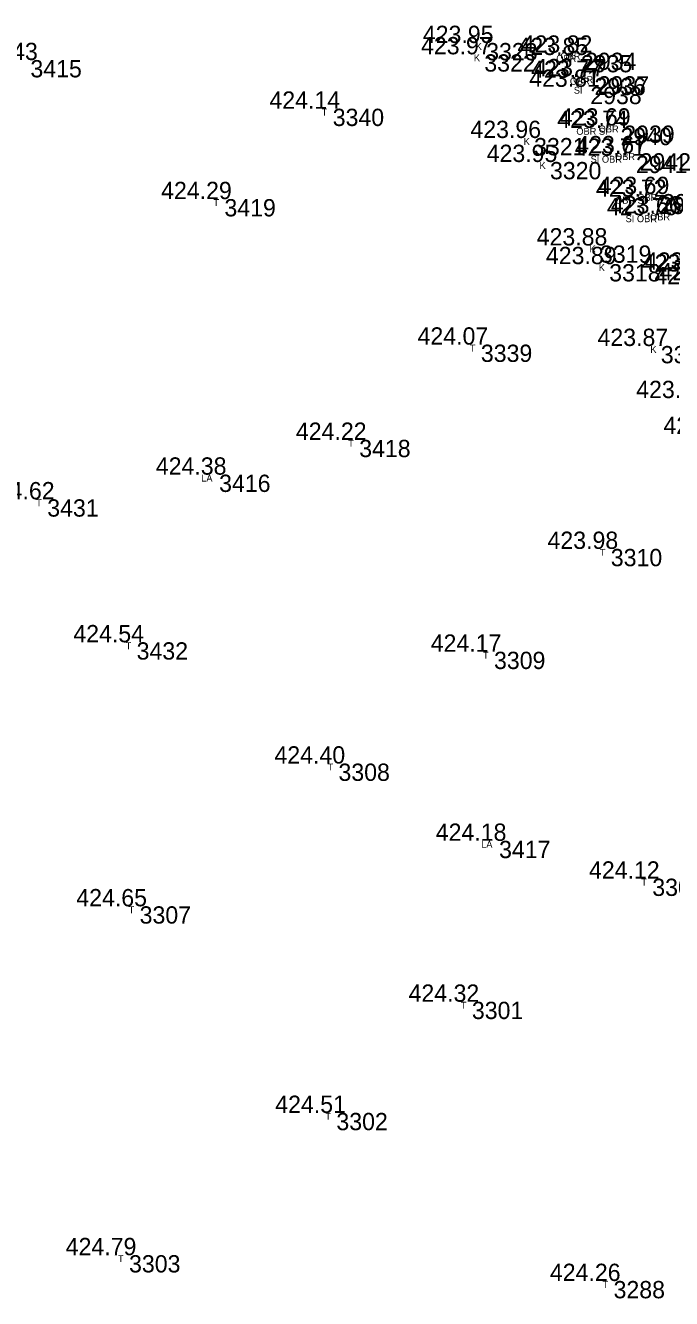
# Model space of a CAD drawing. Extents: x -639390 to -639075, y -1138747 to -1138358.
# Drawn here: x -639264.6 to -639236.5, y -1138514.5 to -1138459.3 of the extents above; entities that cross this region are included whole.
import ezdxf

# ---------------------------------------------------------------- set-up
doc = ezdxf.new("R2010")
doc.units = 0
for name, color, linetype in [('Vrstva 11', 7, 'Continuous'), ('Vrstva 12', 7, 'Continuous'), ('Vrstva 13', 7, 'Continuous'), ('Vrstva 57', 7, 'Continuous')]:
    doc.layers.add(name, color=color, linetype=linetype)

msp = doc.modelspace()

# ---------------------------------------------------------------- linework, layer by layer
at = {"layer": 'Vrstva 11'}
for p, q in [((-639244.92, -1138460.58), (-639244.92, -1138460.58)), ((-639244.84, -1138460.09), (-639244.84, -1138460.09)), ((-639240.73, -1138460.61), (-639240.73, -1138460.61)), ((-639240.55, -1138460.51), (-639240.55, -1138460.51)), ((-639240.14, -1138461.6), (-639240.14, -1138461.6)), ((-639240, -1138461.53), (-639240, -1138461.53)), ((-639240.32, -1138461.99), (-639240.32, -1138461.99)), ((-639251.5, -1138462.94), (-639251.5, -1138462.94)), ((-639239.01, -1138463.77), (-639239.01, -1138463.77)), ((-639238.89, -1138463.67), (-639238.89, -1138463.67)), ((-639242.76, -1138464.21), (-639242.76, -1138464.21)), ((-639238.34, -1138464.98), (-639238.34, -1138464.98)), ((-639238.18, -1138464.87), (-639238.18, -1138464.87)), ((-639242.07, -1138465.25), (-639242.07, -1138465.25)), ((-639237.21, -1138466.64), (-639237.21, -1138466.64)), ((-639256.2, -1138466.86), (-639256.2, -1138466.86)), ((-639237.33, -1138466.76), (-639237.33, -1138466.76)), ((-639236.82, -1138467.56), (-639236.82, -1138467.56)), ((-639236.66, -1138467.48), (-639236.66, -1138467.48)), ((-639239.9, -1138468.87), (-639239.9, -1138468.87)), ((-639239.5, -1138469.68), (-639239.5, -1138469.68)), ((-639245.07, -1138473.17), (-639245.07, -1138473.17)), ((-639237.26, -1138473.23), (-639237.26, -1138473.23)), ((-639250.35, -1138477.3), (-639250.35, -1138477.3)), ((-639256.43, -1138478.81), (-639256.43, -1138478.81)), ((-639263.89, -1138479.88), (-639263.89, -1138479.88)), ((-639239.43, -1138482.03), (-639239.43, -1138482.03)), ((-639260.01, -1138486.08), (-639260.01, -1138486.08)), ((-639244.5, -1138486.49), (-639244.5, -1138486.49)), ((-639251.25, -1138491.34), (-639251.25, -1138491.34)), ((-639244.28, -1138494.69), (-639244.28, -1138494.69)), ((-639237.63, -1138496.33), (-639237.63, -1138496.33)), ((-639259.88, -1138497.53), (-639259.88, -1138497.53)), ((-639245.46, -1138501.67), (-639245.46, -1138501.67)), ((-639251.34, -1138506.49), (-639251.34, -1138506.49)), ((-639260.34, -1138512.66), (-639260.34, -1138512.66)), ((-639239.31, -1138513.78), (-639239.31, -1138513.78))]:
    msp.add_line(p, q, dxfattribs=at)

# ---------------------------------------------------------------- texts
at = {"layer": 'Vrstva 12'}
for s, p in [('423.95 ', (-639247.31, -1138460.09)), ('424.43 ', (-639267.089, -1138460.83)), ('423.97 ', (-639247.389, -1138460.58)), ('423.85 ', (-639243.2, -1138460.61)), ('423.82 ', (-639243.019, -1138460.51)), ('423.77 ', (-639242.609, -1138461.6)), ('423.77 ', (-639242.469, -1138461.53)), ('423.81 ', (-639242.695, -1138461.99)), ('424.14 ', (-639253.969, -1138462.94)), ('423.74 ', (-639241.479, -1138463.77)), ('423.69 ', (-639241.359, -1138463.67)), ('423.96 ', (-639245.246, -1138464.21)), ('423.95 ', (-639244.54, -1138465.25)), ('423.71 ', (-639240.715, -1138464.98)), ('423.67 ', (-639240.649, -1138464.87)), ('424.29 ', (-639258.669, -1138466.86)), ('423.72 ', (-639239.799, -1138466.76)), ('423.69 ', (-639239.679, -1138466.64)), ('423.70 ', (-639239.319, -1138467.56)), ('423.66 ', (-639239.146, -1138467.48)), ('423.88 ', (-639242.369, -1138468.87)), ('423.89 ', (-639241.969, -1138469.68)), ('423.66 ', (-639237.806, -1138470)), ('423.66 ', (-639237.676, -1138469.92)), ('423.64 ', (-639237.259, -1138470.55)), ('423.54 ', (-639237.039, -1138470.38)), ('424.07 ', (-639247.539, -1138473.17)), ('423.87 ', (-639239.729, -1138473.23)), ('423.84 ', (-639238.049, -1138475.49)), ('424.22 ', (-639252.819, -1138477.3)), ('423.82 ', (-639236.869, -1138477.05)), ('424.38 ', (-639258.899, -1138478.81)), ('424.62 ', (-639266.359, -1138479.88)), ('423.98 ', (-639241.899, -1138482.03)), ('424.54 ', (-639262.479, -1138486.08)), ('424.17 ', (-639246.969, -1138486.49)), ('424.40 ', (-639253.749, -1138491.34)), ('424.18 ', (-639246.749, -1138494.69)), ('424.12 ', (-639240.099, -1138496.33)), ('424.65 ', (-639262.35, -1138497.53)), ('424.32 ', (-639247.929, -1138501.67)), ('424.51 ', (-639253.715, -1138506.49)), ('424.79 ', (-639262.809, -1138512.66)), ('424.26 ', (-639241.796, -1138513.78))]:
    msp.add_text(s, height=0.75, dxfattribs=at).set_placement(p)
at = {"layer": 'Vrstva 13'}
for s, p in [(' 3323', (-639244.84, -1138460.84)), (' 3322', (-639244.92, -1138461.33)), (' 2935', (-639240.73, -1138461.36)), (' 2934', (-639240.55, -1138461.26)), (' 3415', (-639264.62, -1138461.58)), (' 2936', (-639240.14, -1138462.35)), (' 2937', (-639240, -1138462.28)), (' 2938', (-639240.32, -1138462.74)), (' 3340', (-639251.5, -1138463.69)), (' 2940', (-639239.01, -1138464.52)), (' 2939', (-639238.89, -1138464.42)), (' 3321', (-639242.76, -1138464.96)), (' 2941', (-639238.34, -1138465.73)), (' 2942', (-639238.18, -1138465.62)), (' 3320', (-639242.07, -1138466)), (' 2943', (-639237.21, -1138467.39)), (' 3419', (-639256.2, -1138467.61)), (' 2944', (-639237.33, -1138467.51)), (' 3319', (-639239.9, -1138469.62)), (' 3318', (-639239.5, -1138470.43)), (' 3339', (-639245.07, -1138473.92)), (' 3317', (-639237.26, -1138473.98)), (' 3418', (-639250.35, -1138478.05)), (' 3416', (-639256.43, -1138479.56)), (' 3431', (-639263.89, -1138480.63)), (' 3310', (-639239.43, -1138482.78)), (' 3432', (-639260.01, -1138486.83)), (' 3309', (-639244.5, -1138487.24)), (' 3308', (-639251.25, -1138492.09)), (' 3417', (-639244.28, -1138495.44)), (' 3300', (-639237.63, -1138497.08)), (' 3307', (-639259.88, -1138498.28)), (' 3301', (-639245.46, -1138502.42)), (' 3302', (-639251.34, -1138507.24)), (' 3303', (-639260.34, -1138513.41)), (' 3288', (-639239.31, -1138514.53))]:
    msp.add_text(s, height=0.75, dxfattribs=at).set_placement(p)
at = {"layer": 'Vrstva 57'}
for s, p in [('K', (-639245.095, -1138460.88)), ('K', (-639245.015, -1138460.39)), ('OBR', (-639241.519, -1138460.91)), ('OBR', (-639241.339, -1138460.81)), ('OBR', (-639240.929, -1138461.9)), ('OBR', (-639240.789, -1138461.83)), ('SI', (-639240.758, -1138462.29)), ('T', (-639251.7, -1138463.24)), ('OBR SI', (-639240.648, -1138464.07)), ('OBR', (-639239.679, -1138463.97)), ('K', (-639242.935, -1138464.51)), ('SI OBR', (-639240.029, -1138465.28)), ('OBR', (-639238.969, -1138465.17)), ('K', (-639242.245, -1138465.55)), ('OBR', (-639237.999, -1138466.94)), ('T', (-639256.4, -1138467.16)), ('OBR SI', (-639238.968, -1138467.06)), ('SI OBR', (-639238.509, -1138467.86)), ('OBR', (-639237.449, -1138467.78)), ('K', (-639240.075, -1138469.17)), ('K', (-639239.675, -1138469.98)), ('T', (-639245.27, -1138473.47)), ('K', (-639237.435, -1138473.53)), ('T', (-639250.55, -1138477.6)), ('LA', (-639256.93, -1138479.11)), ('T', (-639264.09, -1138480.18)), ('T', (-639239.63, -1138482.33)), ('T', (-639260.21, -1138486.38)), ('T', (-639244.7, -1138486.79)), ('T', (-639251.45, -1138491.64)), ('LA', (-639244.78, -1138494.99)), ('T', (-639237.83, -1138496.63)), ('T', (-639260.08, -1138497.83)), ('T', (-639245.66, -1138501.97)), ('T', (-639251.54, -1138506.79)), ('T', (-639260.54, -1138512.96)), ('T', (-639239.51, -1138514.08))]:
    msp.add_text(s, height=0.3, dxfattribs=at).set_placement(p)

doc.saveas('drawing.dxf')
